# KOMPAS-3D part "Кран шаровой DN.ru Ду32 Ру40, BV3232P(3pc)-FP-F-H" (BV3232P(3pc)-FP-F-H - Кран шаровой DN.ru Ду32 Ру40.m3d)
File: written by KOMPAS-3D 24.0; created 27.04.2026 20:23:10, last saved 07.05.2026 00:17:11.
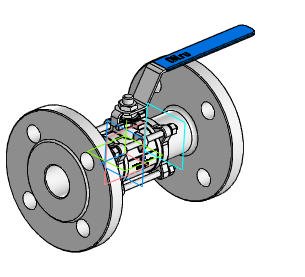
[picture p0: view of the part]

Document properties: Автор: Максим; Полное имя файла: BVxxP(3pc)-FP-F-H - Кран шаровой DN.ru Ду32 Ру40.cdw

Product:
- Body: Тело 1  | qty 1
    Масса: 4.838938
- Part/product: Кран шаровой DN.ru Ду32 Ру40  | designation BV3232P(3pc)-FP-F-H
    Масса: 5.095
    Раздел спецификации: Прочие изделия
    Форматы листов документа: A2
    Примечание: D160-22804

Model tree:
1. Операция без истории:1
2. Эскиз:1  (with: Ребро.Операция без истории:1)
3. Элемент выдавливания:1
     Расстояние 1 = 9
4. Эскиз:2  (with: Грань.Операция без истории:1)
5. Элемент выдавливания:2
     Расстояние 2 = 25
6. Эскиз:3  (with: Грань.Элемент выдавливания:2)
7. Элемент выдавливания:3  (with: Грань.Операция без истории:1)
     Расстояние 1 = 18.5
8. Эскиз:4  (with: Грань.Операция без истории:1)
9. Элемент выдавливания:4
     Расстояние 1 = 7
10. Фаска:1  (with: Ребро.Элемент выдавливания:4)
     Угол = 45; Длина 1 = 1; Длина 2 = 1
11. Скругление:1  (with: Ребро.Элемент выдавливания:1)
     Радиус = 2.5
12. Скругление:2  (with: Ребро.Элемент выдавливания:1)
     Радиус = 5
13. Эскиз:6  (with: Ребро.Элемент выдавливания:1)
14. Элемент выдавливания:5
     Расстояние 1 = 19
15. Фаска:2  (with: Ребро.Элемент выдавливания:5)
     Угол = 45; Длина 1 = 4; Длина 2 = 4
16. Скругление:3  (with: Ребро.Элемент выдавливания:1)
     Радиус = 2.5
17. Скругление:4  (with: Ребро.Элемент выдавливания:1)
     Радиус = 5
18. Эскиз:7  (with: Ребро.Элемент выдавливания:5)
19. Элемент выдавливания:6
     Расстояние 1 = 20
20. Скругление:5  (with: Ребро.Элемент выдавливания:6)
     Радиус = 6.25
21. Скругление:6  (with: Ребро.Элемент выдавливания:6)
     Радиус = 1
22. Смещенная плоскость:1
     Расстояние = -53
23. Эскиз:8  (with: Ребро.Операция без истории:1)
24. Элемент выдавливания:7
     Расстояние 1 = 17
25. Зеркальный массив:1
26. Экземпляр ( 1 )
27. Экземпляр ( 2 )  (with: Элемент выдавливания:7)
28. Эскиз:9  (with: Грань.Операция без истории:1, Ребро.Операция без истории:1)
29. Элемент выдавливания:8  (with: Грань.Операция без истории:1)
     Расстояние 2 = 180
30. Эскиз:10  (with: Грань.Операция без истории:1)
31. Элемент выдавливания:9
     Расстояние 1 = 10
32. Эскиз:11  (with: Грань.Операция без истории:1)
33. Элемент выдавливания:10
     Расстояние 1 = 0.2
34. Эскиз:12  (with: Грань.Операция без истории:1)
35. Элемент выдавливания:11
     Расстояние 1 = 0.2
36. Эскиз:13  (with: Грань.Элемент выдавливания:6, Ребро.Элемент выдавливания:6, Ребро.Скругление:6)
37. Элемент выдавливания:12
     Расстояние 2 = 0.2

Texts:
  BV3232P(3pc)-FP-F-H
  DN32 PN40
